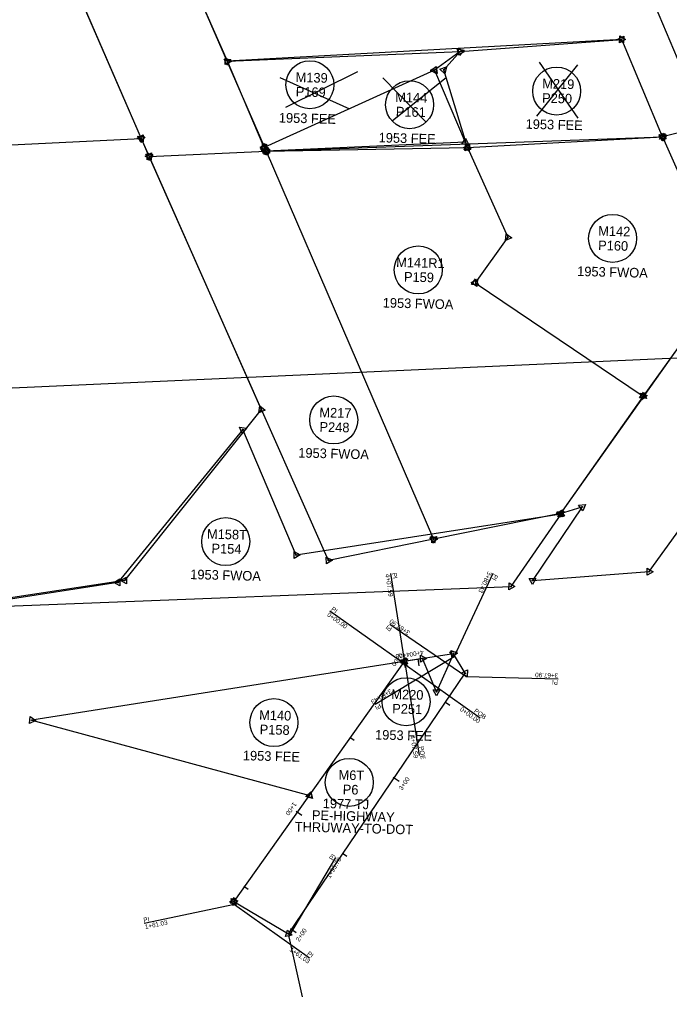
# Model space of a CAD drawing. Extents: x 325018 to 414989, y 1517547 to 1550415.
# Drawn here: x 359748 to 360104, y 1524413 to 1524943 of the extents above; entities that cross this region are included whole.
import ezdxf

# ---------------------------------------------------------------- set-up
doc = ezdxf.new("R2010")
doc.units = 0
for name, color, linetype in [('ACSC_P_T', 7, 'Continuous'), ('ACSCT_P', 7, 'Continuous'), ('ACSR_P_T', 7, 'Continuous'), ('ACSRT_P', 7, 'Continuous'), ('Level 56', 7, 'Continuous'), ('MEE', 7, 'Continuous'), ('MHB', 7, 'Continuous'), ('MHBWOA', 7, 'Continuous'), ('MPL', 7, 'Continuous'), ('MRBL2', 7, 'Continuous'), ('MRBL3', 7, 'Continuous'), ('S_C', 7, 'Continuous'), ('XDEFAULT_P', 7, 'Continuous')]:
    doc.layers.add(name, color=color, linetype=linetype)

msp = doc.modelspace()

# ---------------------------------------------------------------- linework, layer by layer
at = {"layer": 'ACSCT_P'}
for points in [[(359959.14, 1524590.41), (359951.4, 1524640.22)], [(359985.98, 1524594.59), (360007.3, 1524640.26)], [(359959.14, 1524590.41), (359918.08, 1524619.64)], [(359992.46, 1524583.86), (359950.79, 1524612.22)], [(359985.98, 1524594.59), (359942.83, 1524568.55)], [(359959.14, 1524590.41), (360000.2, 1524561.19)], [(359959.14, 1524590.41), (359966.88, 1524540.61)], [(359992.46, 1524583.86), (360042.84, 1524582.48)], [(359895.57, 1524441.5), (359921.33, 1524484.82)], [(359865.77, 1524459.22), (359816.45, 1524448.81)], [(359865.77, 1524459.22), (359906.83, 1524430)], [(359895.57, 1524441.5), (359906.49, 1524392.3)]]:
    msp.add_lwpolyline(points, dxfattribs=at)
at = {"layer": 'ACSRT_P'}
for points in [[(359960.7, 1524589.3), (359957.58, 1524591.53)], [(359959.43, 1524588.52), (359958.84, 1524592.31)], [(359959.43, 1524588.52), (359958.84, 1524592.31)], [(359966.94, 1524589.68), (359966.35, 1524593.48)], [(359981.2, 1524569.87), (359983.58, 1524568.25)], [(359931.32, 1524548.84), (359928.97, 1524550.51)], [(359952.67, 1524528.81), (359955.84, 1524526.65)], [(359902.72, 1524507.83), (359899.59, 1524510.05)], [(359924.93, 1524487.2), (359927.31, 1524485.58)], [(359873.34, 1524467.37), (359870.99, 1524469.04)], [(359896.4, 1524446.14), (359899.58, 1524443.98)]]:
    msp.add_lwpolyline(points, dxfattribs=at)
at = {"layer": 'Level 56'}
for centre in [(359907.09, 1524907.26), (360042.07, 1524903.82), (359961.65, 1524896.39), (360072.68, 1524823.27), (359966.34, 1524806.08), (359920.14, 1524724.06), (359861.03, 1524657.6), (359959.71, 1524570.03), (359887.39, 1524558.67), (359928.61, 1524525.99)]:
    msp.add_circle(centre, 13.12, dxfattribs=at)
at = {"layer": 'MEE'}
for p, q in [((359985.59, 1524596.32), (359976.34, 1524575.53)), ((359968.63, 1524593.63), (359958.75, 1524592.11)), ((359976.34, 1524575.53), (359968.63, 1524593.63)), ((359865.53, 1524460.81), (359895.35, 1524443.13))]:
    msp.add_line(p, q, dxfattribs=at)
for points in [[(359967.57, 1524591.73), (359967.51, 1524595.51)], [(359967.51, 1524595.51), (359970.81, 1524593.67)], [(359983.63, 1524597.29), (359987.4, 1524597.53)], [(359985.72, 1524594.14), (359983.63, 1524597.29)], [(359987.4, 1524597.53), (359985.72, 1524594.14)], [(359956.57, 1524592.05), (359959.78, 1524594.04)], [(359959.89, 1524590.26), (359956.57, 1524592.05)], [(359959.78, 1524594.04), (359959.89, 1524590.26)], [(359970.81, 1524593.67), (359967.57, 1524591.73)], [(359989.9, 1524585.65), (359993.22, 1524587.46)], [(359993.12, 1524583.68), (359989.9, 1524585.65)], [(359993.22, 1524587.46), (359993.12, 1524583.68)], [(359976.32, 1524573.36), (359974.46, 1524576.64)], [(359974.46, 1524576.64), (359978.24, 1524576.61)], [(359978.24, 1524576.61), (359976.32, 1524573.36)], [(359863.35, 1524460.83), (359866.64, 1524462.68)], [(359863.54, 1524459.9), (359865.73, 1524462.98)], [(359865.73, 1524462.98), (359867.31, 1524459.55)], [(359866.64, 1524462.68), (359866.6, 1524458.91)], [(359866.6, 1524458.91), (359863.35, 1524460.83)], [(359867.31, 1524459.55), (359863.54, 1524459.9)], [(359893.75, 1524441.65), (359894.88, 1524445.25)], [(359897.43, 1524442.47), (359893.75, 1524441.65)], [(359894.88, 1524445.25), (359897.43, 1524442.47)]]:
    msp.add_lwpolyline(points, dxfattribs=at)
for centre, radius in [((359985.59, 1524596.32), 0.227), ((359958.75, 1524592.11), 0.227), ((359968.63, 1524593.63), 0.227), ((359992.07, 1524585.6), 0.227), ((359976.34, 1524575.53), 0.227), ((359865.53, 1524460.81), 1.09), ((359865.53, 1524460.81), 1.09), ((359895.35, 1524443.13), 0.227)]:
    msp.add_circle(centre, radius, dxfattribs=at)
at = {"layer": 'MHB'}
for p, q in [((359632.96, 1525295.24), (359814.81, 1524877.96)), ((359819.26, 1524868.15), (359632.96, 1525295.24)), ((359771.61, 1525127.27), (359883.19, 1524871.01)), ((359989.34, 1524925.41), (360077.64, 1524932.06)), ((359861.97, 1524920.11), (359989.34, 1524925.41)), ((359989.34, 1524925.41), (359975.31, 1524915.18)), ((359980.3, 1524915.4), (359989.34, 1524925.41)), ((359882.1, 1524872.96), (359861.97, 1524920.11)), ((359975.31, 1524915.18), (359882.1, 1524872.96)), ((359975.31, 1524915.18), (359992.08, 1524875.89)), ((359993.22, 1524872.94), (359980.3, 1524915.4)), ((359992.08, 1524875.89), (359883.19, 1524871.01)), ((359883.19, 1524871.01), (359882.1, 1524872.96)), ((359958.75, 1524592.11), (359754.98, 1524559.96)), ((359754.98, 1524559.96), (359906.98, 1524518.72))]:
    msp.add_line(p, q, dxfattribs=at)
for points in [[(360075.46, 1524932.11), (360078.77, 1524933.91)], [(360078.68, 1524930.14), (360075.46, 1524932.11)], [(360078.77, 1524933.91), (360078.68, 1524930.14)], [(359987.69, 1524926.83), (359991.4, 1524926.13)], [(359988.93, 1524923.26), (359987.69, 1524926.83)], [(359988.13, 1524923.6), (359988.39, 1524927.36)], [(359991.52, 1524925.26), (359988.13, 1524923.6)], [(359988.39, 1524927.36), (359991.52, 1524925.26)], [(359991.4, 1524926.13), (359988.93, 1524923.26)], [(359861.89, 1524917.93), (359860.13, 1524921.27)], [(359860.13, 1524921.27), (359863.91, 1524921.12)], [(359863.91, 1524921.12), (359861.89, 1524917.93)], [(359973.12, 1524915.17), (359976.39, 1524917.07)], [(359976.4, 1524913.3), (359973.12, 1524915.17)], [(359973.15, 1524914.84), (359976.1, 1524917.21)], [(359976.67, 1524913.47), (359973.15, 1524914.84)], [(359976.1, 1524917.21), (359976.67, 1524913.47)], [(359976.39, 1524917.07), (359976.4, 1524913.3)], [(359978.18, 1524915.88), (359981.78, 1524917.01)], [(359980.96, 1524913.32), (359978.18, 1524915.88)], [(359981.78, 1524917.01), (359980.96, 1524913.32)], [(359813.05, 1524879.25), (359816.81, 1524878.83)], [(359814.56, 1524875.79), (359813.05, 1524879.25)], [(359816.81, 1524878.83), (359814.56, 1524875.79)], [(359990.15, 1524874.87), (359992.16, 1524878.07)], [(359992.16, 1524878.07), (359993.93, 1524874.73)], [(360098.12, 1524879.71), (360101.89, 1524879.92)], [(360100.18, 1524876.55), (360098.12, 1524879.71)], [(360098.32, 1524880.04), (360102.07, 1524879.57)], [(360099.79, 1524876.56), (360098.32, 1524880.04)], [(360102.07, 1524879.57), (360099.79, 1524876.56)], [(360101.89, 1524879.92), (360100.18, 1524876.55)], [(359879.93, 1524873.18), (359883.37, 1524874.74)], [(359883, 1524870.98), (359879.93, 1524873.18)], [(359880.1, 1524872.11), (359882.37, 1524875.13)], [(359883.85, 1524871.66), (359880.1, 1524872.11)], [(359880.2, 1524871.9), (359882.14, 1524875.15)], [(359883.98, 1524871.85), (359880.2, 1524871.9)], [(359880.83, 1524871.19), (359881.2, 1524874.95)], [(359884.28, 1524872.75), (359880.83, 1524871.19)], [(359881.2, 1524874.95), (359884.28, 1524872.75)], [(359881.26, 1524869.99), (359883.26, 1524873.19)], [(359882.13, 1524869.11), (359882.07, 1524872.89)], [(359882.07, 1524872.89), (359885.37, 1524871.05)], [(359885.37, 1524871.05), (359882.13, 1524869.11)], [(359882.14, 1524875.15), (359883.98, 1524871.85)], [(359882.37, 1524875.13), (359883.85, 1524871.66)], [(359883.37, 1524874.74), (359883, 1524870.98)], [(359883.26, 1524873.19), (359885.04, 1524869.86)], [(359993.93, 1524874.73), (359990.15, 1524874.87)], [(359991.97, 1524871.15), (359992.3, 1524874.92)], [(359995.39, 1524872.75), (359991.97, 1524871.15)], [(359992.3, 1524874.92), (359995.39, 1524872.75)], [(359818.1, 1524866.3), (359818.23, 1524870.07)], [(359821.44, 1524868.08), (359818.1, 1524866.3)], [(359818.23, 1524870.07), (359821.44, 1524868.08)], [(359885.04, 1524869.86), (359881.26, 1524869.99)], [(359956.71, 1524592.9), (359960.44, 1524593.49)], [(359959.09, 1524589.96), (359956.71, 1524592.9)], [(359960.44, 1524593.49), (359959.09, 1524589.96)], [(359753.79, 1524558.13), (359753.99, 1524561.91)], [(359757.16, 1524559.84), (359753.79, 1524558.13)], [(359753.99, 1524561.91), (359757.16, 1524559.84)], [(359904.87, 1524518.16), (359907.55, 1524520.82)], [(359907.55, 1524520.82), (359908.52, 1524517.17)], [(359908.52, 1524517.17), (359904.87, 1524518.16)]]:
    msp.add_lwpolyline(points, dxfattribs=at)
for centre, radius in [((360077.64, 1524932.06), 0.227), ((359989.34, 1524925.41), 0.227), ((359989.34, 1524925.41), 0.227), ((359861.97, 1524920.11), 0.227), ((359975.31, 1524915.18), 0.227), ((359975.31, 1524915.18), 0.227), ((359980.3, 1524915.4), 0.227), ((359814.81, 1524877.96), 1.09), ((359992.08, 1524875.89), 0.227), ((360100.06, 1524878.72), 1.09), ((360100.06, 1524878.72), 1.09), ((359882.1, 1524872.96), 1.09), ((359882.1, 1524872.97), 1.09), ((359882.11, 1524872.96), 1.09), ((359882.1, 1524872.97), 1.09), ((359883.19, 1524871.01), 0.227), ((359883.19, 1524871.01), 0.227), ((359993.22, 1524872.94), 0.227), ((359819.26, 1524868.15), 0.227), ((359958.75, 1524592.11), 1.09), ((359754.98, 1524559.96), 0.227), ((359906.98, 1524518.72), 1.09)]:
    msp.add_circle(centre, radius, dxfattribs=at)
at = {"layer": 'MHBWOA'}
for p, q in [((360204.22, 1524898.78), (360044.21, 1524673.02)), ((360092.69, 1524641.16), (360280.21, 1524901.81)), ((360149.8, 1524891.82), (360100.06, 1524878.72)), ((359185.58, 1524846.77), (359814.81, 1524877.96)), ((359814.81, 1524877.96), (359880.51, 1524729.75)), ((359993.22, 1524872.94), (360100.06, 1524878.72)), ((360100.06, 1524878.72), (360134.61, 1524800.19)), ((359883.19, 1524871.01), (359993.22, 1524872.94)), ((359883.19, 1524871.01), (359974.78, 1524658.9)), ((359993.22, 1524872.94), (360015.43, 1524823.88)), ((359917.24, 1524647.31), (359819.26, 1524868.15)), ((360015.43, 1524823.88), (359997.53, 1524799.06)), ((359997.53, 1524799.06), (360089.39, 1524737.1)), ((360134.61, 1524800.19), (360089.39, 1524737.1)), ((360089.39, 1524737.1), (360044.21, 1524673.02)), ((359880.51, 1524729.75), (359805.62, 1524636.3)), ((359870.39, 1524718.81), (359802.12, 1524635.25)), ((359899.6, 1524650.23), (359870.39, 1524718.81)), ((360056.07, 1524676.55), (360028.84, 1524636.29)), ((360044.21, 1524673.02), (360056.07, 1524676.55)), ((360044.5, 1524672.49), (359899.6, 1524650.23)), ((360044.21, 1524673.02), (359974.78, 1524658.9)), ((360017.1, 1524633.08), (360044.5, 1524672.49)), ((359974.78, 1524658.9), (359917.24, 1524647.31)), ((360028.84, 1524636.29), (360092.69, 1524641.16)), ((359805.62, 1524636.3), (359589.86, 1524603.62)), ((359802.12, 1524635.25), (359709.21, 1524620.97)), ((359709.21, 1524620.97), (360017.1, 1524633.08))]:
    msp.add_line(p, q, dxfattribs=at)
for points in [[(359812.63, 1524878.02), (359815.95, 1524879.81)], [(359815.85, 1524876.04), (359812.63, 1524878.02)], [(359815.95, 1524879.81), (359815.85, 1524876.04)], [(360097.88, 1524878.78), (360101.2, 1524880.58)], [(360101.1, 1524876.8), (360097.88, 1524878.78)], [(360098.26, 1524877.5), (360099.9, 1524880.9)], [(360102.03, 1524877.78), (360098.26, 1524877.5)], [(360099.9, 1524880.9), (360102.03, 1524877.78)], [(360101.2, 1524880.58), (360101.1, 1524876.8)], [(359881.01, 1524871.09), (359884.35, 1524872.86)], [(359884.21, 1524869.08), (359881.01, 1524871.09)], [(359883.09, 1524868.83), (359881.36, 1524872.19)], [(359881.36, 1524872.19), (359885.13, 1524872.01)], [(359885.13, 1524872.01), (359883.09, 1524868.83)], [(359884.35, 1524872.86), (359884.21, 1524869.08)], [(359991.03, 1524873.02), (359994.38, 1524874.78)], [(359994.23, 1524871), (359991.03, 1524873.02)], [(359991.39, 1524871.74), (359993.1, 1524875.11)], [(359995.16, 1524871.95), (359991.39, 1524871.74)], [(359993.1, 1524875.11), (359995.16, 1524871.95)], [(359994.38, 1524874.78), (359994.23, 1524871)], [(359819.19, 1524865.96), (359817.4, 1524869.29)], [(359817.4, 1524869.29), (359821.18, 1524869.18)], [(359821.18, 1524869.18), (359819.19, 1524865.96)], [(360014.16, 1524822.11), (360014.53, 1524825.87)], [(360017.6, 1524823.66), (360014.16, 1524822.11)], [(360014.53, 1524825.87), (360017.6, 1524823.66)], [(359995.35, 1524799.2), (359998.74, 1524800.86)], [(359998.48, 1524797.09), (359995.35, 1524799.2)], [(359995.53, 1524798.16), (359997.74, 1524801.23)], [(359999.29, 1524797.78), (359995.53, 1524798.16)], [(359997.74, 1524801.23), (359999.29, 1524797.78)], [(359998.74, 1524800.86), (359998.48, 1524797.09)], [(360087.4, 1524736.21), (360089.6, 1524739.28)], [(360087.97, 1524738.76), (360091.53, 1524737.5)], [(360088.66, 1524735.05), (360087.97, 1524738.76)], [(360089.6, 1524739.28), (360091.16, 1524735.84)], [(360091.16, 1524735.84), (360087.4, 1524736.21)], [(360091.53, 1524737.5), (360088.66, 1524735.05)], [(359879.18, 1524728.02), (359879.67, 1524731.76)], [(359882.67, 1524729.47), (359879.18, 1524728.02)], [(359879.67, 1524731.76), (359882.67, 1524729.47)], [(359870.08, 1524716.66), (359868.67, 1524720.16)], [(359868.67, 1524720.16), (359872.41, 1524719.63)], [(359872.41, 1524719.63), (359870.08, 1524716.66)], [(360042.03, 1524672.9), (360045.2, 1524674.97)], [(360042.22, 1524673.92), (360045.98, 1524674.29)], [(360042.65, 1524671.33), (360044.43, 1524674.67)], [(360045.98, 1524674.29), (360044.42, 1524670.85)], [(360044.43, 1524674.67), (360046.43, 1524671.46)], [(360045.2, 1524674.97), (360045.4, 1524671.2)], [(360054.07, 1524677.43), (360057.82, 1524677.84)], [(360056.3, 1524674.38), (360054.07, 1524677.43)], [(360057.82, 1524677.84), (360056.3, 1524674.38)], [(360045.4, 1524671.2), (360042.03, 1524672.9)], [(360044.42, 1524670.85), (360042.22, 1524673.92)], [(360046.43, 1524671.46), (360042.65, 1524671.33)], [(359972.71, 1524659.6), (359976.41, 1524660.34)], [(359975.21, 1524656.76), (359972.71, 1524659.6)], [(359973.02, 1524660.2), (359976.77, 1524659.76)], [(359974.52, 1524656.73), (359973.02, 1524660.2)], [(359973.77, 1524656.97), (359973.61, 1524660.74)], [(359973.61, 1524660.74), (359976.96, 1524658.99)], [(359976.96, 1524658.99), (359973.77, 1524656.97)], [(359976.77, 1524659.76), (359974.52, 1524656.73)], [(359976.41, 1524660.34), (359975.21, 1524656.76)], [(359898.54, 1524648.32), (359898.48, 1524652.1)], [(359898.48, 1524652.1), (359901.78, 1524650.26)], [(359901.78, 1524650.26), (359898.54, 1524648.32)], [(359916.24, 1524645.38), (359916.06, 1524649.15)], [(359916.06, 1524649.15), (359919.42, 1524647.41)], [(359919.42, 1524647.41), (359916.24, 1524645.38)], [(360091.58, 1524639.28), (360091.62, 1524643.05)], [(360091.62, 1524643.05), (360094.87, 1524641.13)], [(359803.43, 1524636.31), (359806.71, 1524638.2)], [(359806.71, 1524638.2), (359806.7, 1524634.42)], [(360026.95, 1524637.38), (360030.72, 1524637.39)], [(360028.84, 1524634.11), (360026.95, 1524637.38)], [(360030.72, 1524637.39), (360028.84, 1524634.11)], [(360094.87, 1524641.13), (360091.58, 1524639.28)], [(359799.93, 1524635.26), (359803.21, 1524637.14)], [(359803.2, 1524633.36), (359799.93, 1524635.26)], [(359803.21, 1524637.14), (359803.2, 1524633.36)], [(359806.7, 1524634.42), (359803.43, 1524636.31)], [(360015.96, 1524631.21), (360016.05, 1524634.99)], [(360019.28, 1524633.03), (360015.96, 1524631.21)], [(360016.05, 1524634.99), (360019.28, 1524633.03)]]:
    msp.add_lwpolyline(points, dxfattribs=at)
for centre, radius in [((359814.81, 1524877.96), 0.227), ((360100.06, 1524878.72), 0.227), ((360100.06, 1524878.72), 0.227), ((359883.19, 1524871.01), 0.227), ((359883.19, 1524871.01), 0.227), ((359993.22, 1524872.94), 1.09), ((359993.22, 1524872.94), 0.227), ((359819.26, 1524868.15), 0.227), ((360015.43, 1524823.88), 0.227), ((359997.53, 1524799.05), 1.09), ((359997.52, 1524799.05), 1.09), ((360089.39, 1524737.1), 1.09), ((360089.39, 1524737.1), 0.227), ((359880.51, 1524729.75), 0.227), ((359870.39, 1524718.81), 0.227), ((360056.07, 1524676.55), 0.227), ((360044.21, 1524673.02), 0.227), ((360044.21, 1524673.02), 0.227), ((360044.5, 1524672.49), 0.227), ((359974.77, 1524658.9), 1.09), ((359974.78, 1524658.89), 1.09), ((359974.78, 1524658.9), 0.227), ((359899.6, 1524650.23), 0.227), ((359917.24, 1524647.31), 0.227), ((360092.69, 1524641.16), 0.227), ((359802.12, 1524635.25), 0.227), ((359805.62, 1524636.3), 0.227), ((360017.1, 1524633.08), 0.227), ((360028.84, 1524636.29), 0.227)]:
    msp.add_circle(centre, radius, dxfattribs=at)
at = {"layer": 'MPL'}
for p, q in [((359861.97, 1524920.11), (359771.61, 1525127.27)), ((360077.64, 1524932.06), (359861.97, 1524920.11)), ((360100.06, 1524878.72), (360077.64, 1524932.06)), ((359814.81, 1524877.96), (359819.26, 1524868.15)), ((359883.19, 1524871.01), (360100.06, 1524878.72)), ((359819.26, 1524868.15), (359883.19, 1524871.01))]:
    msp.add_line(p, q, dxfattribs=at)
for points in [[(360076.48, 1524930.21), (360076.62, 1524933.98)], [(360079.82, 1524931.98), (360076.48, 1524930.21)], [(360076.62, 1524933.98), (360079.82, 1524931.98)], [(359860.83, 1524918.26), (359860.94, 1524922.03)], [(359864.16, 1524920.05), (359860.83, 1524918.26)], [(359860.94, 1524922.03), (359864.16, 1524920.05)], [(359812.63, 1524878.01), (359815.95, 1524879.82)], [(359815.85, 1524876.04), (359812.63, 1524878.01)], [(359815.95, 1524879.82), (359815.85, 1524876.04)], [(360099.97, 1524876.54), (360098.23, 1524879.9)], [(360098.23, 1524879.9), (360102, 1524879.73)], [(360102, 1524879.73), (360099.97, 1524876.54)], [(359881.35, 1524869.84), (359883.1, 1524873.19)], [(359883.1, 1524873.19), (359885.12, 1524869.99)], [(359817.07, 1524868.2), (359820.39, 1524870)], [(359820.29, 1524866.23), (359817.07, 1524868.2)], [(359820.39, 1524870), (359820.29, 1524866.23)], [(359885.12, 1524869.99), (359881.35, 1524869.84)]]:
    msp.add_lwpolyline(points, dxfattribs=at)
for centre in [(360077.64, 1524932.06), (359861.97, 1524920.11), (359814.81, 1524877.96), (360100.06, 1524878.72), (359883.19, 1524871.01), (359819.26, 1524868.15)]:
    msp.add_circle(centre, 0.227, dxfattribs=at)
at = {"layer": 'MRBL2'}
msp.add_line((357680.4, 1524649.21), (360123.46, 1524758.65), dxfattribs=at)
at = {"layer": 'MRBL3'}
msp.add_line((359994.63, 1525192.19), (360153.1, 1524814.1), dxfattribs=at)
at = {"layer": 'S_C'}
for p, q in [((360032.45, 1524919.55), (360053.74, 1524889)), ((359933.22, 1524914.38), (359893.66, 1524894.92)), ((360053.43, 1524918.18), (360030.99, 1524890.09)), ((359890.61, 1524911.29), (359928.71, 1524894.07)), ((359946.9, 1524911.04), (359970.69, 1524886.88)), ((359981.9, 1524911.29), (359952.13, 1524887.36))]:
    msp.add_line(p, q, dxfattribs=at)
at = {"layer": 'XDEFAULT_P'}
for p, q in [((359985.59, 1524596.32), (359958.75, 1524592.11)), ((359992.07, 1524585.6), (359985.59, 1524596.32)), ((359958.75, 1524592.11), (359865.53, 1524460.81)), ((359895.35, 1524443.13), (359992.07, 1524585.6))]:
    msp.add_line(p, q, dxfattribs=at)
for points in [[(359984.67, 1524594.34), (359984.34, 1524598.11)], [(359984.34, 1524598.11), (359987.76, 1524596.51)], [(359987.76, 1524596.51), (359984.67, 1524594.34)], [(359956.71, 1524592.9), (359960.44, 1524593.49)], [(359956.71, 1524592.9), (359960.45, 1524593.49)], [(359959.09, 1524589.96), (359956.71, 1524592.9)], [(359959.09, 1524589.96), (359956.71, 1524592.9)], [(359956.76, 1524591.21), (359958.95, 1524594.29)], [(359960.52, 1524590.85), (359956.76, 1524591.21)], [(359958.95, 1524594.29), (359960.52, 1524590.85)], [(359960.44, 1524593.49), (359959.09, 1524589.96)], [(359960.45, 1524593.49), (359959.09, 1524589.96)], [(359989.9, 1524585.65), (359993.22, 1524587.46)], [(359993.12, 1524583.68), (359989.9, 1524585.65)], [(359993.22, 1524587.46), (359993.12, 1524583.68)], [(359753.79, 1524558.13), (359753.99, 1524561.91)], [(359757.16, 1524559.84), (359753.79, 1524558.13)], [(359753.99, 1524561.91), (359757.16, 1524559.84)], [(359904.87, 1524518.16), (359907.55, 1524520.82)], [(359907.55, 1524520.82), (359908.52, 1524517.17)], [(359908.52, 1524517.17), (359904.87, 1524518.16)], [(359864.07, 1524462.43), (359867.66, 1524461.26)], [(359864.85, 1524458.73), (359864.07, 1524462.43)], [(359867.66, 1524461.26), (359864.85, 1524458.73)], [(359893.75, 1524441.65), (359894.88, 1524445.25)], [(359897.43, 1524442.47), (359893.75, 1524441.65)], [(359894.88, 1524445.25), (359897.43, 1524442.47)]]:
    msp.add_lwpolyline(points, dxfattribs=at)
for centre, radius in [((359985.59, 1524596.32), 0.227), ((359958.75, 1524592.11), 1.09), ((359958.75, 1524592.11), 1.09), ((359958.75, 1524592.11), 1.09), ((359992.07, 1524585.6), 0.227), ((359754.98, 1524559.96), 0.227), ((359906.98, 1524518.72), 1.09), ((359865.53, 1524460.81), 0.227), ((359895.35, 1524443.13), 0.227)]:
    msp.add_circle(centre, radius, dxfattribs=at)

# ---------------------------------------------------------------- texts
at = {"layer": 'ACSC_P_T'}
for s, rotation, p in [('4+07.59', 278.8383, (359948.31, 1524639.73)), ('PI', 278.8383, (359952.01, 1524640.31)), ('3+80.43', 244.9735, (360004.47, 1524641.58)), ('PI', 244.9735, (360007.87, 1524639.99)), ('PI', 324.5607, (359918.44, 1524620.15)), ('0+00.00', 324.5607, (359916.26, 1524617.09)), ('PI', 145.7613, (359952.38, 1524610.38)), ('3+67.90', 145.7613, (359962.07, 1524608.32)), ('3+67.90', 178.435, (360042.92, 1524585.61)), ('PI', 178.435, (360042.82, 1524581.86)), ('3+80.43', 211.1086, (359950.96, 1524577.11)), ('PI', 211.1086, (359945.16, 1524569.22)), ('0+00.00', 324.5607, (359988.91, 1524565.39)), ('POB', 324.5607, (359996.59, 1524564.53)), ('4+07.59', 278.8383, (359962.03, 1524551.47)), ('POE', 278.8383, (359966.75, 1524545.52)), ('1+95.70', 59.2664, (359918.07, 1524473.23)), ('PI', 59.2664, (359919.59, 1524483.13)), ('PI', 11.9136, (359816.33, 1524449.43)), ('1+61.03', 11.9136, (359817.1, 1524445.76)), ('1+61.03', 324.5607, (359895.72, 1524434.07)), ('PI', 324.5607, (359905.29, 1524431.86))]:
    msp.add_text(s, height=2.501, rotation=rotation, dxfattribs=at).set_placement(p)
at = {"layer": 'ACSR_P_T'}
for s, rotation, p in [('0+00', 234.5607, (359956.06, 1524596.86)), ('4+08', 188.8383, (359961.52, 1524597.11)), ('4+08', 188.8383, (359961.52, 1524597.11)), ('4+00', 188.8383, (359969.1, 1524598.29)), ('3+00', 55.7613, (359957.49, 1524521.38)), ('1+00', 234.5607, (359898.07, 1524515.38)), ('2+00', 55.7613, (359901.21, 1524438.68))]:
    msp.add_text(s, height=2.501, rotation=rotation, dxfattribs=at).set_placement(p)
at = {"layer": 'Level 56'}
for s, height, p in [('M139', 5.249, (359899.23, 1524908.78)), ('M219', 5.249, (360034.12, 1524905.34)), ('P169', 5.249, (359899.28, 1524900.9)), ('M144', 5.249, (359953.72, 1524897.91)), ('P250', 5.249, (360034.05, 1524897.46)), ('1953 FEE', 5.249, (359890.06, 1524886.68)), ('P161', 5.249, (359954.04, 1524890.03)), ('1953 FEE', 5.249, (360025.04, 1524883.24)), ('1953 FEE', 5.249, (359944.63, 1524875.81)), ('M142', 5.249, (360064.75, 1524824.79)), ('P160', 5.249, (360064.71, 1524816.91)), ('M141R1', 5.249, (359954.22, 1524807.71)), ('1953 FWOA', 5.249, (360053.24, 1524802.75)), ('P159', 5.249, (359958.5, 1524799.72)), ('1953 FWOA', 5.249, (359946.89, 1524785.56)), ('M217', 5.249, (359912.21, 1524725.58)), ('P248', 5.249, (359912.3, 1524717.7)), ('1953 FWOA', 5.249, (359900.69, 1524703.55)), ('M158T', 5.249, (359850.75, 1524659.18)), ('P154', 5.249, (359853.21, 1524651.24)), ('1953 FWOA', 5.249, (359841.59, 1524637.08)), ('M220', 5.249, (359951.59, 1524571.55)), ('P251', 5.249, (359952.07, 1524563.66)), ('M140', 5.249, (359879.27, 1524560.19)), ('P158', 5.249, (359879.57, 1524552.31)), ('1953 FEE', 5.249, (359942.69, 1524549.45)), ('1953 FEE', 5.249, (359870.37, 1524538.09)), ('M6T', 5.249, (359922.72, 1524527.46)), ('P6', 5.249, (359925.01, 1524519.52)), ('1977 TJ', 5.249, (359914.08, 1524511.92)), ('PE-HIGHWAY', 5.249, (359908.15, 1524505.5)), ('THRUWAY-TO-DOT', 5.2493, (359898.76, 1524499.17))]:
    msp.add_text(s, height=height, rotation=358.5141, dxfattribs=at).set_placement(p)

doc.saveas('drawing.dxf')
